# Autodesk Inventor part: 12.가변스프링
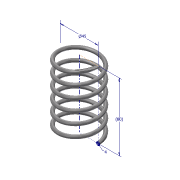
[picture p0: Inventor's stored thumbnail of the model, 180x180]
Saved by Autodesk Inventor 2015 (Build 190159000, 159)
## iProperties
Created: 2016-06
Part Number: 12.가변스프링
Material: 스테인레스 스틸
Document SubType Name: Modeling
Designer: sys
Density: 8 g/cm^3
Appearance: 반연마
Mass: 84.3547 g
Surface Area: 106.584 cm^2
Volume: 10.5443 cm^3
Author: sys
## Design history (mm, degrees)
sketch "스케치1"
  geometry: L1 (0, 0)-(-22.5, 0); L2 (-22.5, 0)-(-22.5, 75.25); L3 (-22.5, 75.25)-(0, 75.25); L4 (0, 75.25)-(0, 0); C1 r 2 at (-22.5, 0)
  constraints: 8 end point, 2 parallel, 1 centre point, 1 coincident, 1 horizontal, 1 perpendicular
  dimensions: "d0" = 75.24962 distance between parallel lines of L1 L3 (derived); "d1" = 45 diameter of L2 L4; "d2" = 4 diameter of C1
feature "코일1" sketch "스케치1" pitch "d3" = 10; turns "d5" = 6; dims "d4" = 75.24962 (= d0), "d6" = 0, angle "d7" = 90 deg, angle "d8" = 90 deg, "d9" = 0, "d10" = 0
sketch "스케치2"
  geometry: L1 (24.5, 0)-(20.5, 0) reference; L2 (24.5, 0)-(20.5, 0) reference; 1 further point
  constraints: 2 horizontal alignment
extrude "돌출1" cut sketch "스케치2" stored distance "d11" = 10; taper "d12" = 0 deg
node "작업 평면1"
sketch "스케치3"
  geometry: L1 (20.5, 0)-(24.5, 0) reference; 1 further point
  constraints: 1 horizontal alignment
extrude "돌출2" cut sketch "스케치3" stored distance "d14" = 10; taper "d15" = 0 deg
node "솔리드1"
node "절단 모서리 투영1"
node "절단 모서리 투영2"
node "절단 모서리 투영3"
